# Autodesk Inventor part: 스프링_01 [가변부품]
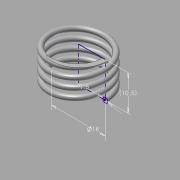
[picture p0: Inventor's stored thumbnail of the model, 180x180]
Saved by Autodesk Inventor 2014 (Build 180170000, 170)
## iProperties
Created: 2015-07
Part Number: 스프링_01 [가변부품]
Material: 강철, 연강
Document SubType Name: Modeling
Designer: Administrator
Mass: 2.70831 g
Surface Area: 9.40604 cm^2
Volume: 0.344568 cm^3
Density: 7.86 g/cm^3
Appearance: 강철
Author: Administrator
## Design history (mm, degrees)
sketch "스케치1"
  geometry: L1 (0, 0)-(-8, 0); L2 (-8, 0)-(-8, 10.5); L3 (-8, 10.5)-(0, 10.5); L4 (0, 10.5)-(0, 0); C1 r 0.75 at (-8, 0)
  constraints: 8 end point, 2 parallel, 1 centre point, 1 coincident, 1 horizontal, 1 perpendicular
  dimensions: "d0" = 16 diameter of L2 L4; "d1" = 10.5 distance of L1.end L2.end (derived); "d2" = 1.5 diameter of C1
feature "코일1" sketch "스케치1" pitch "d3" = 10; turns "d5" = 4; dims "d4" = 10.5 (= d1), "d6" = 0, angle "d7" = 90 deg, angle "d8" = 90 deg, "d9" = 0, "d10" = 0
node "작업 평면1"
sketch "스케치2"
  geometry: L1 (-0.75, 0)-(0.75, 0) reference; 1 further point
  constraints: 1 horizontal alignment
extrude "돌출1" cut sketch "스케치2" distance "d11" = 10; taper "d12" = 0 deg
node "작업 평면2"
sketch "스케치3"
  geometry: L1 (0.75, 0)-(-0.75, 0) reference; 1 further point
  constraints: 1 horizontal alignment
extrude "돌출2" cut sketch "스케치3" distance "d13" = 10; taper "d14" = 0 deg
node "솔리드1"
node "절단 모서리 투영1"
node "절단 모서리 투영2"
